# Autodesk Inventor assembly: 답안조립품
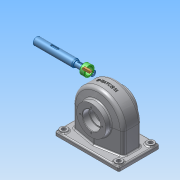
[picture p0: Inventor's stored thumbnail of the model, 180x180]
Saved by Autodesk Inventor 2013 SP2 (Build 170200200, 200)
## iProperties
Created: 2025-05
Part Number: 답안조립품
Document SubType Name: Assembly
Designer: a
Author: a
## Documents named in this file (5)
- C:\Users\a\Desktop\750503V1006\답안조립품.iam
- C:\Users\a\Desktop\750503V1006\본체.ipt
- C:\Users\a\Desktop\750503V1006\축.ipt
- C:\Users\a\Desktop\750503V1006\칼라.ipt
- C:\Users\a\Desktop\750503V1006\평행 키 5x5x18.ipt
